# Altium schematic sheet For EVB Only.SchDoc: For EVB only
size 419 x 266 mm; Date: May 24, 2007; DrawnBy: Yossi Har-Nov; Engineer: Yossi Har-Nov; Revision: 1.0; SheetNumber: 3; SheetTotal: 3
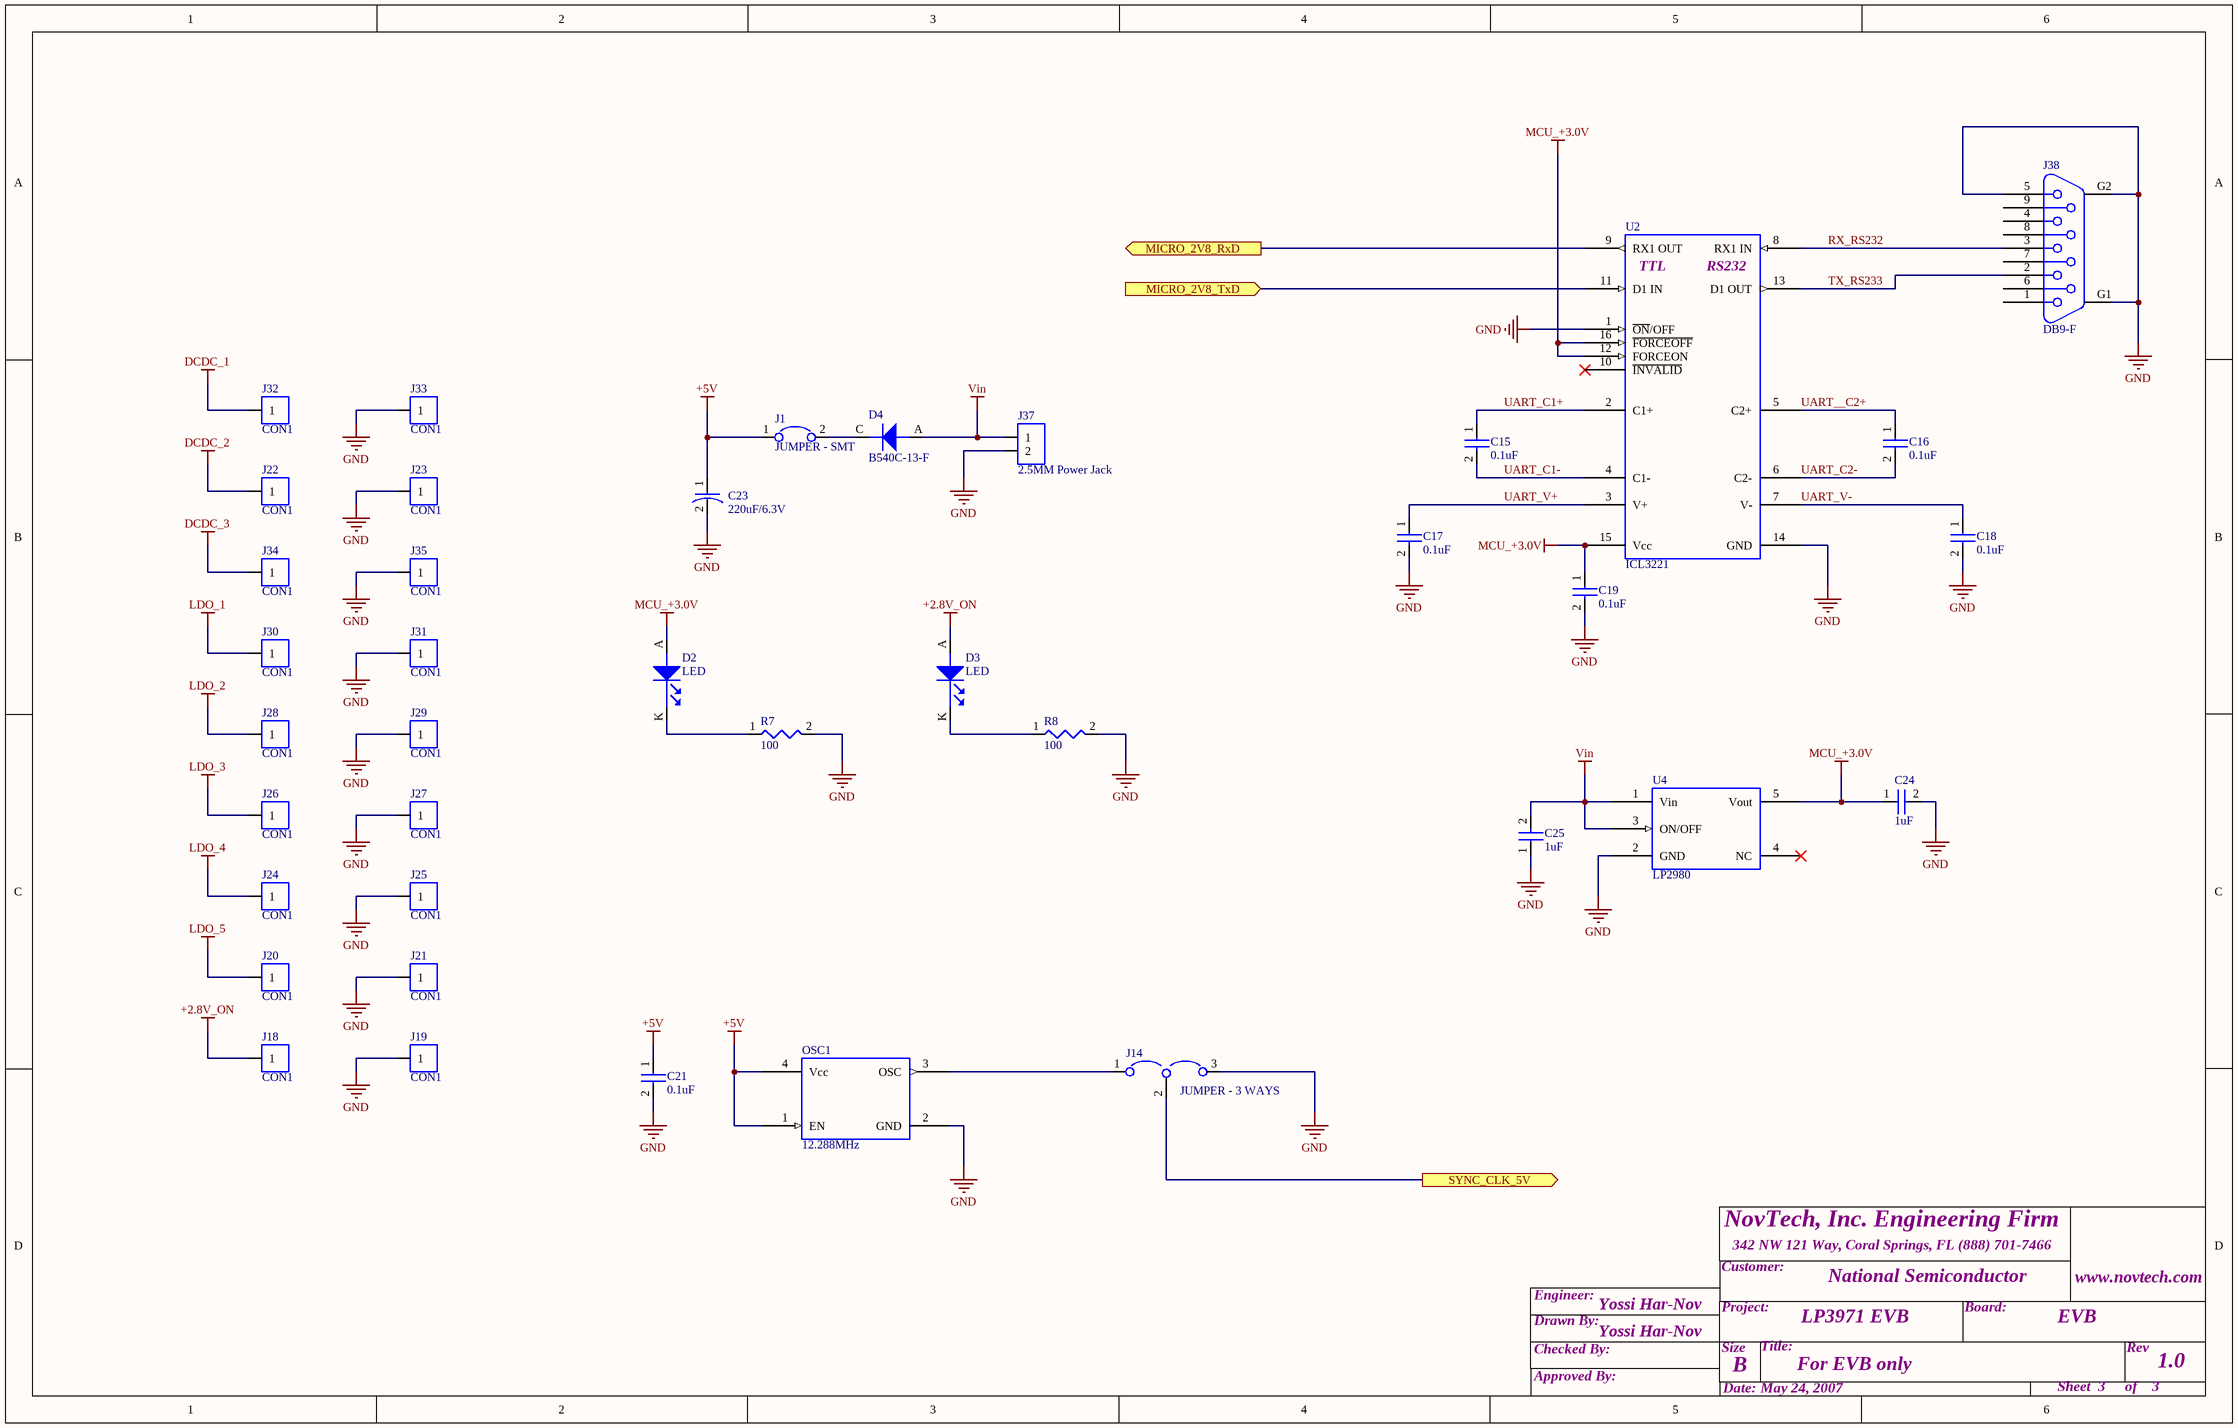
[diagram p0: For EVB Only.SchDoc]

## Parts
C15  0.1uF  [0603_C]
C16  0.1uF  [0603_C]
C17  0.1uF  [0603_C]
C18  0.1uF  [0603_C]
C19  0.1uF  [0603_C]
C21  0.1uF  [0603_C]
C23  220uF/6.3V  [C CASE (6032-28)]
C24  1uF  [0603_C]
C25  1uF  [0603_C]
D2  LED  [0603_LED]
D3  LED  [0603_LED]
D4  B540C-13-F  [SMC]
J1  JUMPER - SMT  [BH2-NP]
J14  JUMPER - 3 WAYS  [BH3-NP]
J18  CON1  [BH1-NP - 46MIL]
J19  CON1  [BH1-NP - 46MIL]
J20  CON1  [BH1-NP - 46MIL]
J21  CON1  [BH1-NP - 46MIL]
J22  CON1  [BH1-NP - 46MIL]
J23  CON1  [BH1-NP - 46MIL]
J24  CON1  [BH1-NP - 46MIL]
J25  CON1  [BH1-NP - 46MIL]
J26  CON1  [BH1-NP - 46MIL]
J27  CON1  [BH1-NP - 46MIL]
J28  CON1  [BH1-NP - 46MIL]
J29  CON1  [BH1-NP - 46MIL]
J30  CON1  [BH1-NP - 46MIL]
J31  CON1  [BH1-NP - 46MIL]
J32  CON1  [BH1-NP - 46MIL]
J33  CON1  [BH1-NP - 46MIL]
J34  CON1  [BH1-NP - 46MIL]
J35  CON1  [BH1-NP - 46MIL]
J37  2.5MM Power Jack  [PJ-002B (POWER JACK)]
J38  DB9-F  [DB9_F_318]
OSC1  12.288MHz  [OSC_SMT_7.3X4.8]
R7  100  [0603_R]
R8  100  [0603_R]
U2  ICL3221  [TSSOP_16]
U4  LP2980  [SOT23-5]

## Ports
MICRO_2V8_RxD (out), MICRO_2V8_TxD (in), SYNC_CLK_5V (out)

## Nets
+2.8V_ON: D3.A J18.1
+5V: C21.1 C23.1 J1.1 OSC1.1(EN) OSC1.4(Vcc)
DCDC_1: J32.1
DCDC_2: J22.1
DCDC_3: J34.1
GND: C17.2 C18.2 C19.2 C21.2 C23.2 C24.2 C25.1 J14.3 J19.1 J21.1 J23.1 J25.1 J27.1 J29.1 J31.1 J33.1 J35.1 J37.2 J38.5 J38.G1 J38.G2 OSC1.2(GND) R7.2 R8.2 U2.1(~{ON}/OFF) U2.14(GND) U4.2(GND)
LDO_1: J30.1
LDO_2: J28.1
LDO_3: J26.1
LDO_4: J24.1
LDO_5: J20.1
MCU_+3.0V: C19.1 C24.1 D2.A U2.12(FORCEON) U2.15(Vcc) U2.16(~{FORCEOFF}) U4.5(Vout)
Vin: C25.2 D4.A J37.1 U4.1(Vin) U4.3(ON/OFF)
MICRO_2V8_RxD: U2.9(RX1_OUT) ; port MICRO_2V8_RxD
MICRO_2V8_TxD: U2.11(D1_IN) ; port MICRO_2V8_TxD
RX_RS232: J38.3 U2.8(RX1_IN)
SYNC_CLK_5V: J14.2 ; port SYNC_CLK_5V
TX_RS233: J38.2 U2.13(D1_OUT)
UART__C2+: C16.1 U2.5(C2+)
UART_C1+: C15.1 U2.2(C1+)
UART_C1-: C15.2 U2.4(C1-)
UART_C2-: C16.2 U2.6(C2-)
UART_V+: C17.1 U2.3(V+)
UART_V-: C18.1 U2.7(V-)
NetD2_K: D2.K R7.1
NetD3_K: D3.K R8.1
NetD4_C: D4.C J1.2
NetJ14_1: J14.1 OSC1.3(OSC)

Not connected (* = marked no-connect by the designer): J38 1 4 6 7 8 9; U2 10(~{INVALID})*; U4 4(NC)*

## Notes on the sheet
- National Semiconductor
- LP3971 EVB
- EVB

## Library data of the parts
C15-C19 C21 C24 C25 = CAP_0603: Capasitor 0603footprint; Right: 20; Bottom: 10
C23 = CAP_TANT: PART: T494C227M006AT; MFG: KEMET
D4 = DIODE: MFG: Diode Inc.
J14 = JUMPER - SMT 3 WAYS: JUMPER - SMT
J37 = CON2: PART: PJ-002B; MFG: CUI Inc
OSC1 = OSCILLATOR: PART: CWX815-12.288M; MFG: Connor-Winfield
R7 R8 = RESISOTR 0603: Resistor 0603 footprint
U2 = ICL3221: IC TXRX SGL RS232 3-5.5V; PART: ICL3221EIVZ; MFG: Intersil
U4 = LP2980: Micropowe 50mA LDO; PART: LP2980AIM5-3.0; MFG: NATIONAL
